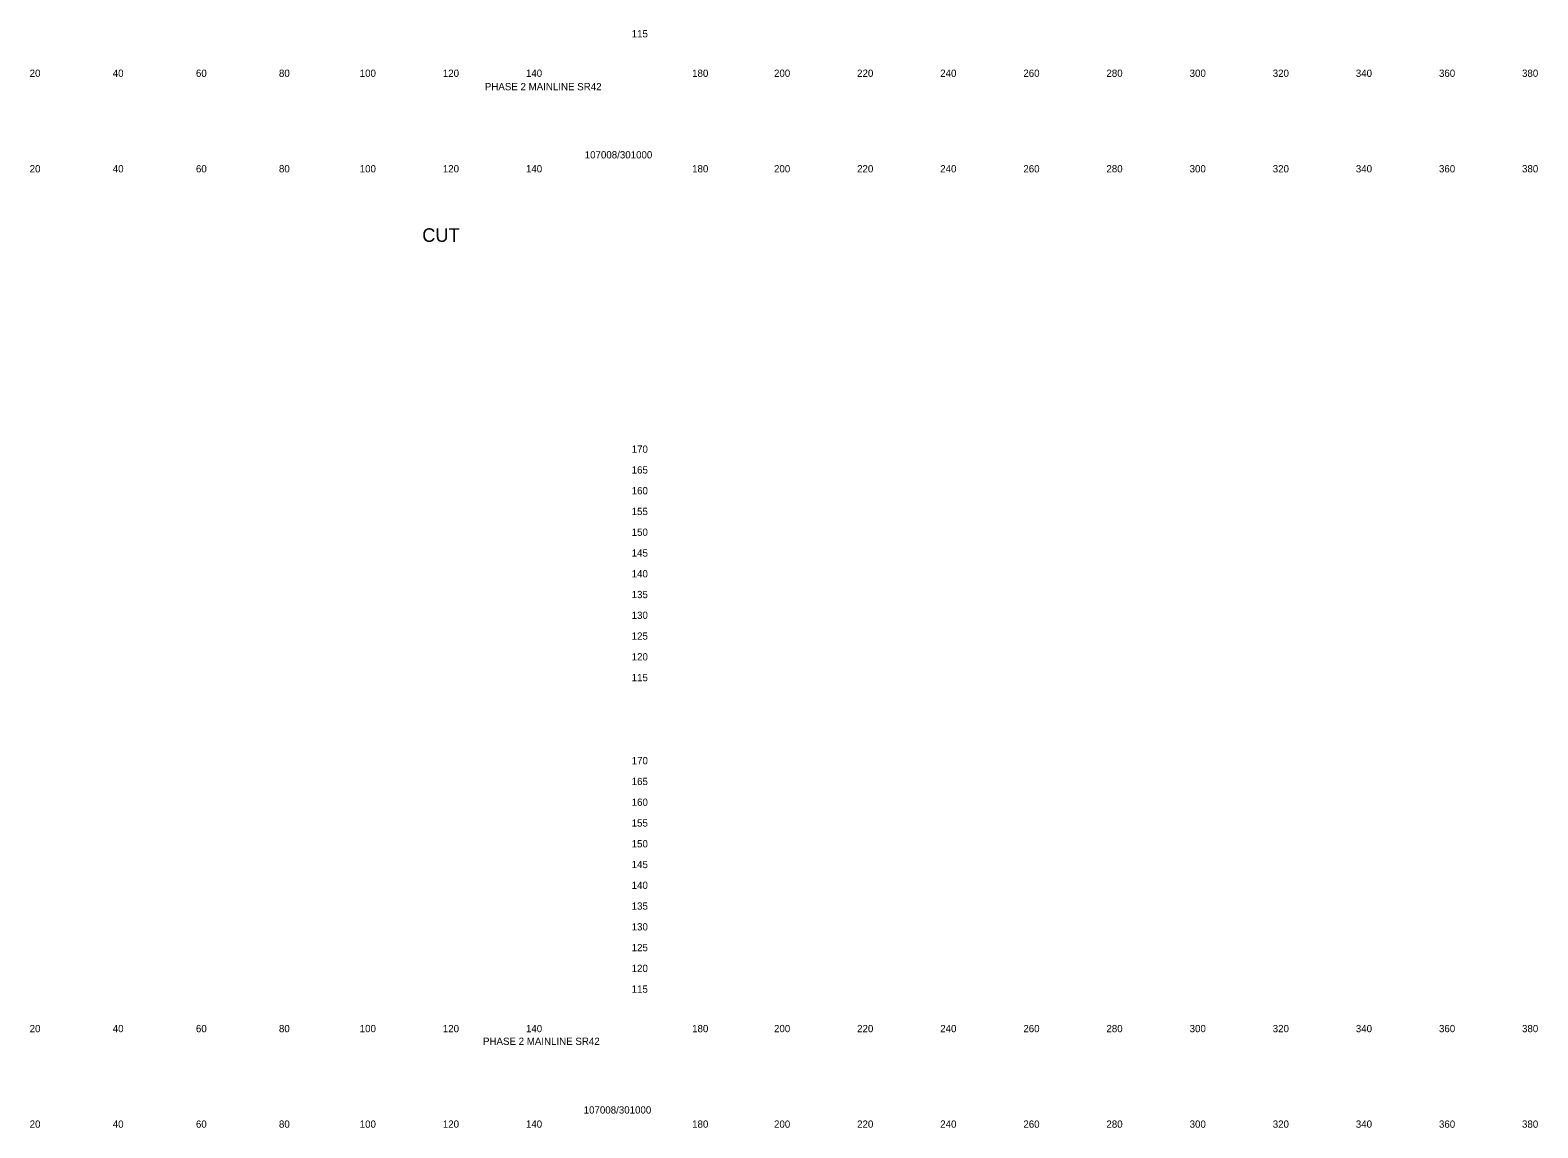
# Model space of a CAD drawing. Extents: x 21281 to 22024, y 6472 to 15208.
# Drawn here: x 21661.4 to 22024.2, y 13582.3 to 13846.6 of the extents above; entities that cross this region are included whole.
import ezdxf

# ---------------------------------------------------------------- set-up
doc = ezdxf.new("R2010")
doc.units = 0
doc.layers.add('XS_SHEET_LABELS_ELEVATION', color=7, linetype='Continuous')
doc.layers.add('XS_SHEET_LABELS_OFFSET', color=7, linetype='Continuous')

msp = doc.modelspace()

# ---------------------------------------------------------------- texts
at = {"layer": 'XS_SHEET_LABELS_ELEVATION'}
for s, p in [('  115  ', (21804.84, 13844.84)), ('  170  ', (21804.84, 13744.84)), ('  165  ', (21804.84, 13739.84)), ('  160  ', (21804.84, 13734.84)), ('  155  ', (21804.84, 13729.84)), ('  150  ', (21804.84, 13724.84)), ('  145  ', (21804.84, 13719.84)), ('  140  ', (21804.84, 13714.84)), ('  135  ', (21804.84, 13709.84)), ('  130  ', (21804.84, 13704.84)), ('  125  ', (21804.84, 13699.84)), ('  120  ', (21804.84, 13694.84)), ('  115  ', (21804.84, 13689.84)), ('  170  ', (21804.84, 13669.84)), ('  165  ', (21804.84, 13664.84)), ('  160  ', (21804.84, 13659.84)), ('  155  ', (21804.84, 13654.84)), ('  150  ', (21804.84, 13649.84)), ('  145  ', (21804.84, 13644.84)), ('  140  ', (21804.84, 13639.84)), ('  135  ', (21804.84, 13634.84)), ('  130  ', (21804.84, 13629.84)), ('  125  ', (21804.84, 13624.84)), ('  120  ', (21804.84, 13619.84)), ('  115  ', (21804.84, 13614.84))]:
    msp.add_text(s, height=1.75, dxfattribs=at).set_placement(p)
at = {"layer": 'XS_SHEET_LABELS_OFFSET'}
for s, height, p in [('  20  ', 1.75, (21659.95, 13835.34)), ('  40  ', 1.75, (21679.95, 13835.34)), ('  60  ', 1.75, (21699.97, 13835.34)), ('  80  ', 1.75, (21719.95, 13835.34)), ('  100  ', 1.75, (21739.39, 13835.34)), ('  120  ', 1.75, (21759.39, 13835.34)), ('  140  ', 1.75, (21779.39, 13835.34)), ('  180  ', 1.75, (21819.39, 13835.34)), ('  200  ', 1.75, (21839.1, 13835.34)), ('  220  ', 1.75, (21859.1, 13835.34)), ('  240  ', 1.75, (21879.1, 13835.34)), ('  260  ', 1.75, (21899.11, 13835.34)), ('  280  ', 1.75, (21919.1, 13835.34)), ('  300  ', 1.75, (21939.13, 13835.34)), ('  320  ', 1.75, (21959.13, 13835.34)), ('  340  ', 1.75, (21979.13, 13835.34)), ('  360  ', 1.75, (21999.14, 13835.34)), ('  380  ', 1.75, (22019.13, 13835.34)), ('PHASE 2 MAINLINE SR42', 1.75, (21770.8, 13832.11)), ('107008/301000', 1.75, (21794.84, 13815.7)), ('  20  ', 1.75, (21659.95, 13812.34)), ('  40  ', 1.75, (21679.95, 13812.34)), ('  60  ', 1.75, (21699.97, 13812.34)), ('  80  ', 1.75, (21719.95, 13812.34)), ('  100  ', 1.75, (21739.39, 13812.34)), ('  120  ', 1.75, (21759.39, 13812.34)), ('  140  ', 1.75, (21779.39, 13812.34)), ('  180  ', 1.75, (21819.39, 13812.34)), ('  200  ', 1.75, (21839.1, 13812.34)), ('  220  ', 1.75, (21859.1, 13812.34)), ('  240  ', 1.75, (21879.1, 13812.34)), ('  260  ', 1.75, (21899.11, 13812.34)), ('  280  ', 1.75, (21919.1, 13812.34)), ('  300  ', 1.75, (21939.13, 13812.34)), ('  320  ', 1.75, (21959.13, 13812.34)), ('  340  ', 1.75, (21979.13, 13812.34)), ('  360  ', 1.75, (21999.14, 13812.34)), ('  380  ', 1.75, (22019.13, 13812.34)), ('CUT', 3.273, (21755.74, 13795.61)), ('  20  ', 1.75, (21659.95, 13605.34)), ('  40  ', 1.75, (21679.95, 13605.34)), ('  60  ', 1.75, (21699.97, 13605.34)), ('  80  ', 1.75, (21719.95, 13605.34)), ('  100  ', 1.75, (21739.39, 13605.34)), ('  120  ', 1.75, (21759.39, 13605.34)), ('PHASE 2 MAINLINE SR42', 1.75, (21770.36, 13602.28)), ('  140  ', 1.75, (21779.39, 13605.34)), ('  180  ', 1.75, (21819.39, 13605.34)), ('  200  ', 1.75, (21839.1, 13605.34)), ('  220  ', 1.75, (21859.1, 13605.34)), ('  240  ', 1.75, (21879.1, 13605.34)), ('  260  ', 1.75, (21899.11, 13605.34)), ('  280  ', 1.75, (21919.1, 13605.34)), ('  300  ', 1.75, (21939.13, 13605.34)), ('  320  ', 1.75, (21959.13, 13605.34)), ('  340  ', 1.75, (21979.13, 13605.34)), ('  360  ', 1.75, (21999.14, 13605.34)), ('  380  ', 1.75, (22019.13, 13605.34)), ('107008/301000', 1.75, (21794.59, 13585.75)), ('  20  ', 1.75, (21659.95, 13582.34)), ('  40  ', 1.75, (21679.95, 13582.34)), ('  60  ', 1.75, (21699.97, 13582.34)), ('  80  ', 1.75, (21719.95, 13582.34)), ('  100  ', 1.75, (21739.39, 13582.34)), ('  120  ', 1.75, (21759.39, 13582.34)), ('  140  ', 1.75, (21779.39, 13582.34)), ('  180  ', 1.75, (21819.39, 13582.34)), ('  200  ', 1.75, (21839.1, 13582.34)), ('  220  ', 1.75, (21859.1, 13582.34)), ('  240  ', 1.75, (21879.1, 13582.34)), ('  260  ', 1.75, (21899.11, 13582.34)), ('  280  ', 1.75, (21919.1, 13582.34)), ('  300  ', 1.75, (21939.13, 13582.34)), ('  320  ', 1.75, (21959.13, 13582.34)), ('  340  ', 1.75, (21979.13, 13582.34)), ('  360  ', 1.75, (21999.14, 13582.34)), ('  380  ', 1.75, (22019.13, 13582.34))]:
    msp.add_text(s, height=height, dxfattribs=at).set_placement(p)

doc.saveas('drawing.dxf')
